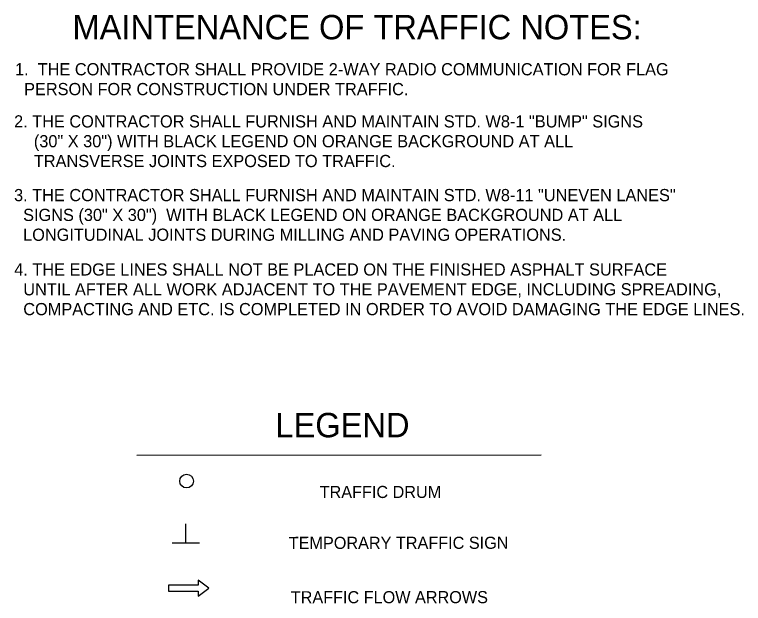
# Model space of a CAD drawing. Extents: x 1930579 to 1939784, y 596179 to 597522.
# Drawn here: x 1937354.3 to 1937712.7, y 597050.7 to 597340.4 of the extents above; entities that cross this region are included whole.
import ezdxf

# ---------------------------------------------------------------- set-up
doc = ezdxf.new("R2010")
doc.units = 0
for name, color, linetype in [('Default', 7, 'Continuous'), ('R_Annotation', 7, 'Continuous'), ('R_MOT', 7, 'Continuous')]:
    doc.layers.add(name, color=color, linetype=linetype)

msp = doc.modelspace()

# ---------------------------------------------------------------- linework, layer by layer
at = {"layer": 'Default'}
msp.add_circle((1937438.9, 597110.88), 3.37, dxfattribs=at)
at = {"layer": 'R_Annotation'}
for p, q in [((1937414.38, 597123.67), (1937613.19, 597123.8)), ((1937438.6, 597080.54), (1937438.6, 597089.76)), ((1937445.32, 597080.34), (1937431.82, 597080.34))]:
    msp.add_line(p, q, dxfattribs=at)
at = {"layer": 'R_MOT'}
msp.add_lwpolyline([(1937444.66, 597054.19), (1937449.85, 597058.19), (1937444.65, 597062.19), (1937444.66, 597059.69), (1937429.94, 597059.68), (1937429.95, 597056.68), (1937444.66, 597056.69)], close=True, dxfattribs=at)

# ---------------------------------------------------------------- texts
at = {"layer": 'R_Annotation'}
for s, height, rotation, p in [('MAINTENANCE OF TRAFFIC NOTES:', 12, 360, (1937382.79, 597328.24)), ('1.  THE CONTRACTOR SHALL PROVIDE 2-WAY RADIO COMMUNICATION FOR FLAG ', 6, 360, (1937354.54, 597310.51)), ('  PERSON FOR CONSTRUCTION UNDER TRAFFIC.', 6, 360, (1937354.54, 597300.76)), ('2. THE CONTRACTOR SHALL FURNISH AND MAINTAIN STD. W8-1 "BUMP" SIGNS', 6, 360, (1937354.07, 597284.87)), (' (30" X 30") WITH BLACK LEGEND ON ORANGE BACKGROUND AT ALL ', 6, 360, (1937361.57, 597275.12)), (' TRANSVERSE JOINTS EXPOSED TO TRAFFIC.', 6, 360, (1937361.57, 597265.37)), ('3. THE CONTRACTOR SHALL FURNISH AND MAINTAIN STD. W8-11 "UNEVEN LANES" ', 6, 360, (1937354.06, 597248.6)), ('  SIGNS (30" X 30")  WITH BLACK LEGEND ON ORANGE BACKGROUND AT ALL ', 6, 360, (1937354.06, 597238.85)), ('  LONGITUDINAL JOINTS DURING MILLING AND PAVING OPERATIONS.', 6, 360, (1937354.06, 597229.1)), ('4. THE EDGE LINES SHALL NOT BE PLACED ON THE FINISHED ASPHALT SURFACE', 6, 360, (1937354.14, 597212)), ('  UNTIL AFTER ALL WORK ADJACENT TO THE PAVEMENT EDGE, INCLUDING SPREADING,', 6, 360, (1937354.14, 597202.25)), ('  COMPACTING AND ETC. IS COMPLETED IN ORDER TO AVOID DAMAGING THE EDGE LINES.', 6, 360, (1937354.14, 597192.5)), ('LEGEND', 12, 0.0388, (1937482.56, 597132.39)), ('TRAFFIC DRUM', 5.9598, 0.0388, (1937504.34, 597102.52)), ('TEMPORARY TRAFFIC SIGN', 5.9598, 0.0388, (1937489.15, 597077.48)), ('TRAFFIC FLOW ARROWS', 5.9598, 0.0388, (1937490.14, 597050.74))]:
    msp.add_text(s, height=height, rotation=rotation, dxfattribs=at).set_placement(p)

doc.saveas('drawing.dxf')
